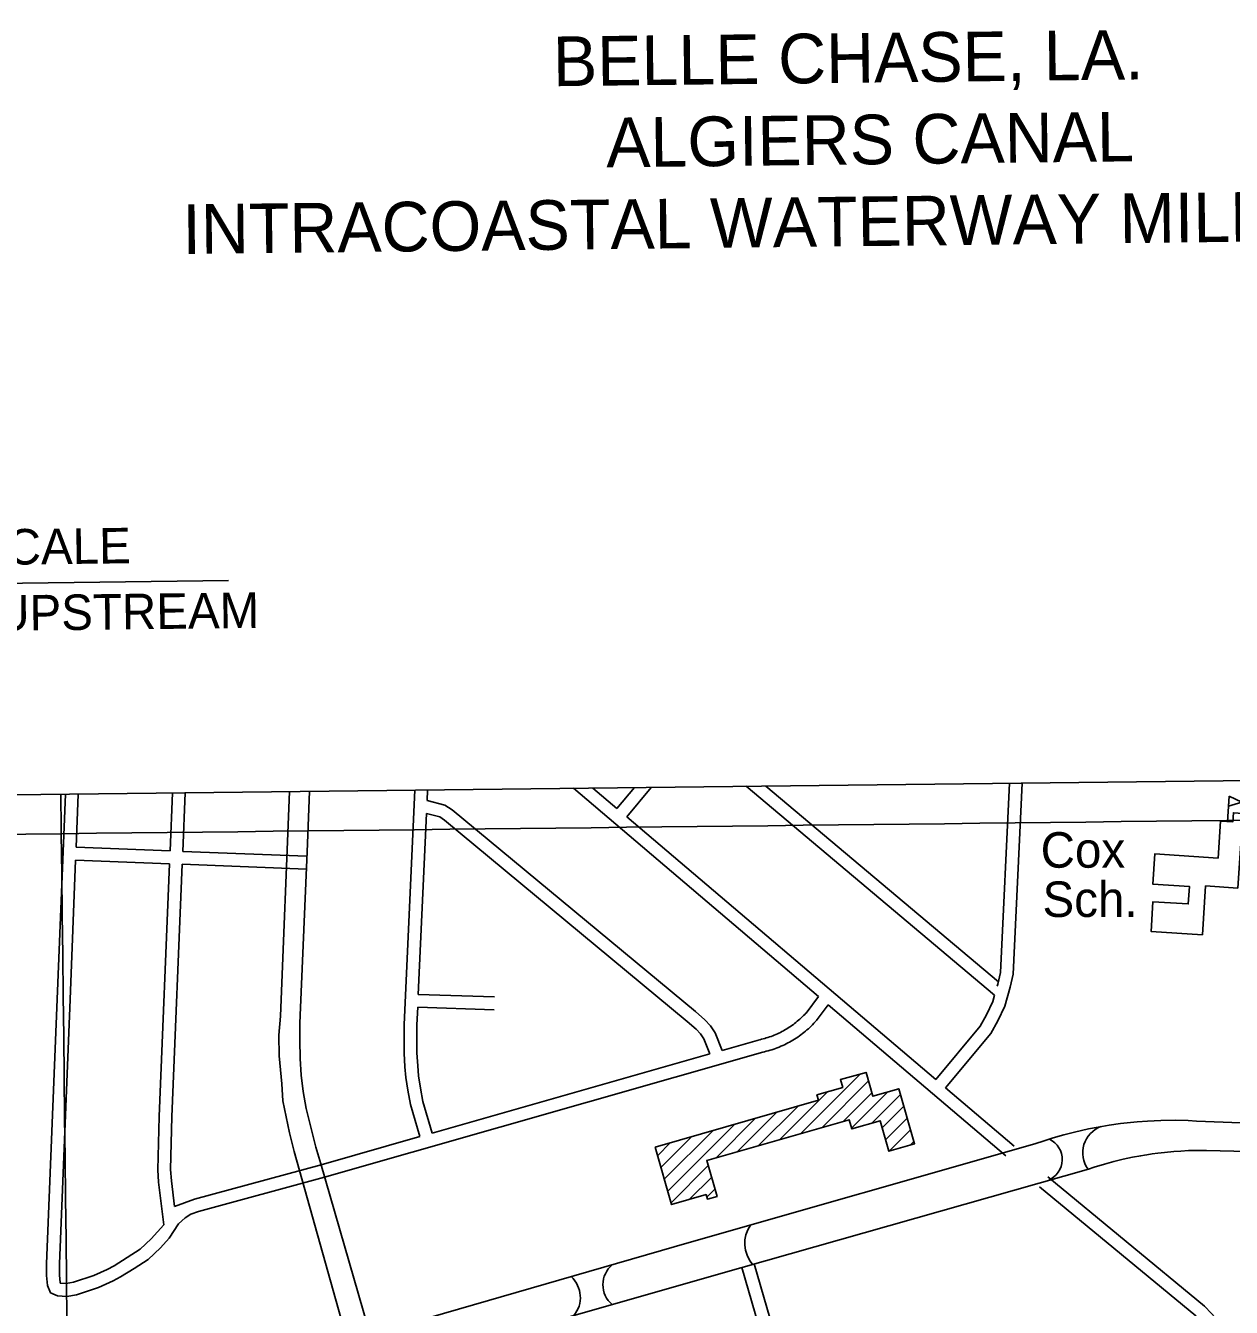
# Model space of a CAD drawing. Extents: x 3683402 to 3721514, y 487807 to 513565.
# Drawn here: x 3692714 to 3695530, y 504296 to 507291 of the extents above; entities that cross this region are included whole.
import ezdxf

# ---------------------------------------------------------------- set-up
doc = ezdxf.new("R2010")
doc.units = 0
for name, color, linetype in [('V-ANNO-SYMB', 7, 'Continuous'), ('V-BLDG-IDEN', 7, 'Continuous'), ('V-BLDG-OTLN', 7, 'Continuous'), ('V-GRID-MAJR', 7, 'Continuous'), ('V-ROAD-CNTR', 7, 'Continuous')]:
    doc.layers.add(name, color=color, linetype=linetype)

msp = doc.modelspace()

# ---------------------------------------------------------------- linework, layer by layer
at = {"layer": 'V-ANNO-SYMB'}
msp.add_line((3691778.6, 505977.4), (3693187.9, 505993.8), dxfattribs=at)
msp.add_lwpolyline([(3687900.3, 511066.8), (3696792.8, 511170.1), (3696858.2, 505541.9), (3687965.7, 505438.5)], close=True, dxfattribs=at)
at = {"layer": 'V-BLDG-OTLN'}
for p, q in [((3695521.8, 505430.2), (3695525.6, 505490.1)), ((3694524.7, 504701.8), (3694664.2, 504841.3)), ((3694574.3, 504716), (3694683.1, 504824.9)), ((3694475.1, 504687.5), (3694586.9, 504799.4)), ((3694623.9, 504730.2), (3694691, 504797.4)), ((3694643.3, 504714.3), (3694728.3, 504799.3)), ((3694690.5, 504726.2), (3694757.5, 504793.2)), ((3694375.9, 504659.1), (3694468.7, 504751.8)), ((3694425.5, 504673.3), (3694518.3, 504766.1)), ((3694714.7, 504715), (3694765.4, 504765.7)), ((3694213.8, 504567.7), (3694369.5, 504723.4)), ((3694326.3, 504644.8), (3694419.1, 504737.6)), ((3694722.6, 504687.5), (3694773.3, 504738.3)), ((3694198, 504622.6), (3694270.3, 504694.9)), ((3694205.9, 504595.2), (3694319.9, 504709.1)), ((3694731.5, 504661.1), (3694781.2, 504710.8)), ((3694190.2, 504650.1), (3694220.7, 504680.7)), ((3694781.1, 504675.3), (3694789.1, 504683.3)), ((3694221.7, 504540.2), (3694308.4, 504627)), ((3694265.1, 504548.3), (3694316.3, 504599.5)), ((3694305.4, 504553.2), (3694324.2, 504572))]:
    msp.add_line(p, q, dxfattribs=at)
for points in [[(3695525.6, 505490.1), (3695554.8, 505476.6), (3695524.1, 505467)], [(3695545.8, 505275.6), (3695470.2, 505280.5), (3695462.8, 505166.3), (3695342.8, 505174.1), (3695347.3, 505243.7), (3695429.8, 505238.3), (3695432.5, 505279.5), (3695346.9, 505285), (3695351.4, 505355.2), (3695499.4, 505345.6), (3695505, 505432), (3695533.7, 505430.1), (3695535.1, 505451.5), (3695557.1, 505450.1)], [(3694184.4, 504670.2), (3694565.9, 504779.7), (3694562.3, 504792.3), (3694622.7, 504809.6), (3694617.4, 504827.9), (3694677.3, 504845), (3694693.3, 504789.3), (3694753.7, 504806.6), (3694790.6, 504678), (3694730.3, 504660.7), (3694709.9, 504731.8), (3694643.8, 504712.8), (3694637.6, 504734.2), (3694305.1, 504638.7), (3694329, 504555.2), (3694306.7, 504548.8), (3694303.6, 504559.3), (3694222.9, 504536.2)]]:
    msp.add_lwpolyline(points, close=True, dxfattribs=at)
at = {"layer": 'V-GRID-MAJR'}
for points in [[(3687515.9, 505342.9), (3692797.3, 505402.5), (3698078.7, 505462.8), (3703360, 505523.8), (3708641.3, 505585.7), (3713922.7, 505648.3), (3719204, 505711.6)], [(3692934.8, 493283.3), (3692866.1, 499341.9), (3692797.3, 505402.5), (3692796.2, 505494.7)]]:
    msp.add_spline(points, degree=3, dxfattribs=at)
at = {"layer": 'V-ROAD-CNTR'}
for points in [[(3693051.3, 505362.3), (3693056.8, 505497.7)], [(3693081.3, 505361.1), (3693086.9, 505498)], [(3693330.4, 505500.9), (3693309.1, 504976.4), (3693305.7, 504931.7), (3693306.4, 504883.3), (3693312.2, 504817.9), (3693314.6, 504778.6), (3693330.4, 504703.7), (3693341.6, 504659.9), (3693705.8, 503360.9), (3693714, 503329.8), (3693719, 503302.1), (3693723.9, 503269.7), (3693725.7, 503233.3), (3693723.7, 503215), (3693721.3, 503184.1), (3693708.7, 503140.5), (3693702.6, 503106.4), (3693699.2, 503066.8), (3693698.2, 503037.7), (3693700.2, 503011.7), (3693702.7, 502985.5), (3693716.6, 502931.8), (3693758.3, 502781.3)], [(3693377.4, 505501.4), (3693371.5, 505360.3), (3693354.8, 504959.9), (3693354.4, 504919.9), (3693355.2, 504877.3), (3693357.5, 504838), (3693362.2, 504800.4), (3693369.2, 504760.8), (3693378.4, 504722.8), (3693392, 504670.1), (3693403.6, 504631.1), (3693777.3, 503336)], [(3693634.9, 504694.8), (3693612.7, 504769.7), (3693606.5, 504803.1), (3693602.3, 504833), (3693599.9, 504858.2), (3693598.1, 504889.8), (3693598.1, 504917.8), (3693598, 504956.8), (3693623, 505504.3)], [(3693651.9, 505480), (3693653.1, 505504.6)], [(3694565.8, 505021.9), (3693993.6, 505508.6)], [(3694095.4, 505461.4), (3694039.3, 505509.1)], [(3694095.4, 505461.4), (3694136.1, 505510.2)], [(3694118.3, 505441.9), (3694175.6, 505510.7)], [(3694977.4, 505025.1), (3694397.4, 505513.3)], [(3694986.4, 505056.7), (3694443.4, 505513.8)], [(3695042, 505520.8), (3695020.7, 505074.5), (3695014, 505043.8), (3695001.4, 504999.8), (3694984.9, 504965.7), (3694968.7, 504936.1), (3694862.9, 504808.6)], [(3695012, 505520.4), (3694990.9, 505078.4), (3694984.9, 505051.2), (3694983.5, 505046.6)], [(3693412.3, 504600.2), (3693118, 504519.7), (3693100, 504513.3), (3693086.9, 504504.9), (3693071, 504490.9), (3693049, 504457.6), (3693029.1, 504434.9), (3692999.9, 504407.8), (3692967.5, 504386.6), (3692935.9, 504367.3), (3692918.4, 504357.5), (3692884.6, 504342), (3692833, 504325.2), (3692810.2, 504321.5), (3692788.8, 504322.7), (3692772.4, 504330), (3692765, 504346.6), (3692763, 504370), (3692763, 504397.9), (3692787.8, 505016.3), (3692807, 505494.8)], [(3692832, 505370.9), (3692837, 505495.1)], [(3694341.2, 504896.3), (3694325.1, 504937.3), (3694314.1, 504953.7), (3694300.8, 504967.8), (3694278.6, 504987), (3693710.5, 505458.3), (3693693.6, 505469.6), (3693651.9, 505480)], [(3693631.3, 505026.9), (3693650.5, 505449.4)], [(3694312.2, 504888.1), (3694298.4, 504923.3), (3694290.6, 504935), (3694280.1, 504946.1), (3694259.2, 504964), (3693692.6, 505434.2), (3693681.3, 505441.7), (3693650.5, 505449.4)], [(3694840, 504828), (3694118.3, 505441.9)], [(3693051.3, 505362.3), (3692832, 505370.9)], [(3693371, 505349.7), (3693081.3, 505361.1)], [(3693036.5, 504488.7), (3693007.5, 504455.9), (3692981.4, 504431.5), (3692951.5, 504412), (3692920.8, 504393.2), (3692904.7, 504384.2), (3692873.7, 504370), (3692825.9, 504354.5), (3692808.7, 504351.7), (3692795.9, 504352.4), (3692795.1, 504352.7), (3692794.5, 504354.2), (3692793, 504371.3), (3692793, 504397.4), (3692817.8, 505015.1), (3692830.8, 505341)], [(3693050, 505332.3), (3692830.8, 505341)], [(3693036.5, 504488.7), (3693024.5, 504588.7), (3693022.6, 504617.5), (3693025.8, 504742.2), (3693050, 505332.3)], [(3693061.6, 504531.3), (3693054.4, 504591.5), (3693052.7, 504618.1), (3693055.7, 504741.2), (3693080, 505331.1)], [(3693369.8, 505319.7), (3693080, 505331.1)], [(3693809.1, 505021.3), (3693631.3, 505026.9)], [(3694536.9, 504983.3), (3694565.8, 505021.9)], [(3694977.4, 505025.1), (3694973.3, 505010.6), (3694958.2, 504979.4), (3694943.8, 504953), (3694840, 504828)], [(3693663.7, 504703.1), (3693641.9, 504776.8), (3693636.1, 504807.9), (3693632.1, 504836.5), (3693629.8, 504860.4), (3693628.1, 504890.6), (3693628.1, 504917.9), (3693628.1, 504956.2), (3693629.9, 504996.9)], [(3693808.2, 504991.3), (3693629.9, 504996.9)], [(3694560.9, 504965.3), (3694588.7, 505002.4)], [(3695003.6, 504649.6), (3694588.7, 505002.4)], [(3694428.8, 504921.3), (3694432.8, 504922.2), (3694436.6, 504923.2), (3694440.4, 504924.2), (3694444.2, 504925.3), (3694448, 504926.5), (3694451.7, 504927.7), (3694455.4, 504929), (3694459.1, 504930.4), (3694462.8, 504931.9), (3694466.4, 504933.4), (3694470, 504935), (3694473.6, 504936.7), (3694477.1, 504938.4), (3694480.6, 504940.2), (3694484.1, 504942.1), (3694487.5, 504944), (3694490.9, 504946), (3694494.3, 504948.1), (3694497.6, 504950.2), (3694500.9, 504952.4), (3694504.1, 504954.6), (3694507.3, 504956.9), (3694510.4, 504959.3), (3694513.5, 504961.7), (3694516.6, 504964.2), (3694519.6, 504966.7), (3694522.6, 504969.3), (3694525.5, 504972), (3694528.3, 504974.7), (3694531.1, 504977.4), (3694533.9, 504980.3), (3694536.6, 504983.2), (3694537.8, 504984.5)], [(3694435.6, 504892.1), (3694439.9, 504893), (3694444.2, 504894.1), (3694448.6, 504895.3), (3694452.9, 504896.6), (3694457.2, 504897.9), (3694461.5, 504899.4), (3694465.7, 504900.9), (3694469.9, 504902.5), (3694474.1, 504904.1), (3694478.3, 504905.9), (3694482.4, 504907.7), (3694486.5, 504909.6), (3694490.5, 504911.6), (3694494.5, 504913.6), (3694498.5, 504915.8), (3694502.4, 504918), (3694506.3, 504920.3), (3694510.2, 504922.6), (3694514, 504925), (3694517.7, 504927.5), (3694521.4, 504930.1), (3694525.1, 504932.8), (3694528.7, 504935.5), (3694532.2, 504938.2), (3694535.7, 504941.1), (3694539.2, 504944), (3694542.6, 504947), (3694545.9, 504950), (3694549.2, 504953.1), (3694552.4, 504956.3), (3694555.5, 504959.5), (3694558.6, 504962.7), (3694559.9, 504964.2)], [(3694341.2, 504896.3), (3694428.1, 504921.1)], [(3693412.4, 504600.2), (3694436.3, 504892.2)], [(3693663.7, 504703.1), (3694312.2, 504888.1)], [(3695023, 504672.4), (3694862.9, 504808.6)], [(3695071.5, 504677.6), (3695093.4, 504685.1), (3695114.4, 504691.7), (3695138.8, 504698.8), (3695164.1, 504705.3), (3695197, 504712.8), (3695219.4, 504717.2), (3695245.1, 504721.5), (3695271.9, 504725.3), (3695310.4, 504729.4), (3695334.5, 504731.2), (3695366, 504732.5), (3695400, 504732.9), (3695429.8, 504732.2), (3695449.4, 504731.2), (3695697.3, 504721.7)], [(3693404.2, 504629.1), (3693634.9, 504694.8)], [(3690741.2, 503791.5), (3691288.9, 503924.4), (3691363.8, 503939.8), (3691394.5, 503943.8), (3691425.1, 503948.1), (3691500.1, 503954.8), (3692494.8, 503976.4), (3692516, 503975.4), (3692533.1, 503975.5), (3692552.9, 503976.5), (3692573.1, 503978.2), (3692603.8, 503982.2), (3692634.2, 503987.7), (3692987.3, 504078.3), (3694263.8, 504447.2), (3695071.5, 504677.6)], [(3695196.5, 504619.1), (3695210.1, 504623.6), (3695234.1, 504630.8), (3695255.9, 504636.7), (3695277.4, 504641.9), (3695299.7, 504646.6), (3695318.8, 504650.2), (3695327.2, 504651.6), (3695333.4, 504652.6), (3695345.7, 504654.5), (3695358.4, 504656.2), (3695374.6, 504658), (3695396.3, 504660.1), (3695412.2, 504661.2), (3695430.4, 504662.1), (3695445, 504662.6), (3695460.8, 504662.7), (3695472.7, 504662.7), (3695695.6, 504656.9)], [(3693404.4, 504629.1), (3693108.9, 504548.3), (3693061.6, 504531.3)], [(3693406.7, 504108.5), (3694326.9, 504371.9), (3695196.5, 504619.1)], [(3695513.3, 503887.7), (3695527.1, 504169.2), (3695526, 504187.9), (3695523.1, 504204.5), (3695519.5, 504223.1), (3695513.1, 504237.1), (3695507.6, 504250.6), (3695498.5, 504265.1), (3695484.1, 504281.4), (3695467.4, 504298.3), (3695101.4, 504600.9)], [(3695483.4, 503889.2), (3695497, 504169), (3695496.1, 504184.4), (3695493.6, 504199), (3695490.7, 504214), (3695485.6, 504225.2), (3695480.8, 504236.9), (3695474.4, 504247.1), (3695462.2, 504260.9), (3695447.1, 504276.2), (3695082.3, 504577.8)], [(3694386.9, 504388.8), (3694620.6, 503583)], [(3694415.7, 504397.2), (3694579.3, 503833.4)]]:
    msp.add_lwpolyline(points, dxfattribs=at)
for centre, radius, start, end in [((3695248.9, 504657), 65.5, 110.5999, 215.5866), ((3695082.3, 504641.4), 53, 293.0111, 63.8861), ((3694469.8, 504445.3), 75.9, 145.6904, 220.4404), ((3694123, 504348.7), 60.6, 129.623, 229.9251), ((3693943.6, 504318.9), 66.2, 320.4299, 47.453)]:
    msp.add_arc(centre, radius, start, end, dxfattribs=at)

# ---------------------------------------------------------------- texts
at = {"layer": 'V-ANNO-SYMB'}
for s, height, rotation, p in [('BELLE CHASE, LA.', 115.999, 0.666, (3693946.4, 507148.9)), ('ALGIERS CANAL', 115.999, 0.666, (3694070.7, 506959.3)), ('INTRACOASTAL WATERWAY MILE 3.7', 115.999, 0.666, (3693080.9, 506756.8)), ('NOT  TO  SCALE', 83, 0.6827, (3692084.4, 506024)), ('VIEW  FROM  UPSTREAM', 83, 0.6827, (3691909.8, 505867.5))]:
    msp.add_text(s, height=height, rotation=rotation, dxfattribs=at).set_placement(p)
at = {"layer": 'V-BLDG-IDEN'}
for s, p in [('Cox', (3695085, 505323.1)), ('Sch.', (3695089.3, 505208))]:
    msp.add_text(s, height=83, dxfattribs=at).set_placement(p)

doc.saveas('drawing.dxf')
